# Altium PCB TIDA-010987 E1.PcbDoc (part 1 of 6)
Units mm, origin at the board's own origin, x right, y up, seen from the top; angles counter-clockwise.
Board outline 154.15 x 103.76 mm, 4 copper layers (5V, GND, MidSupply, -5V), stack 1.787 mm thick; 92 components, 52 nets, 1640 pads, 56 vias.
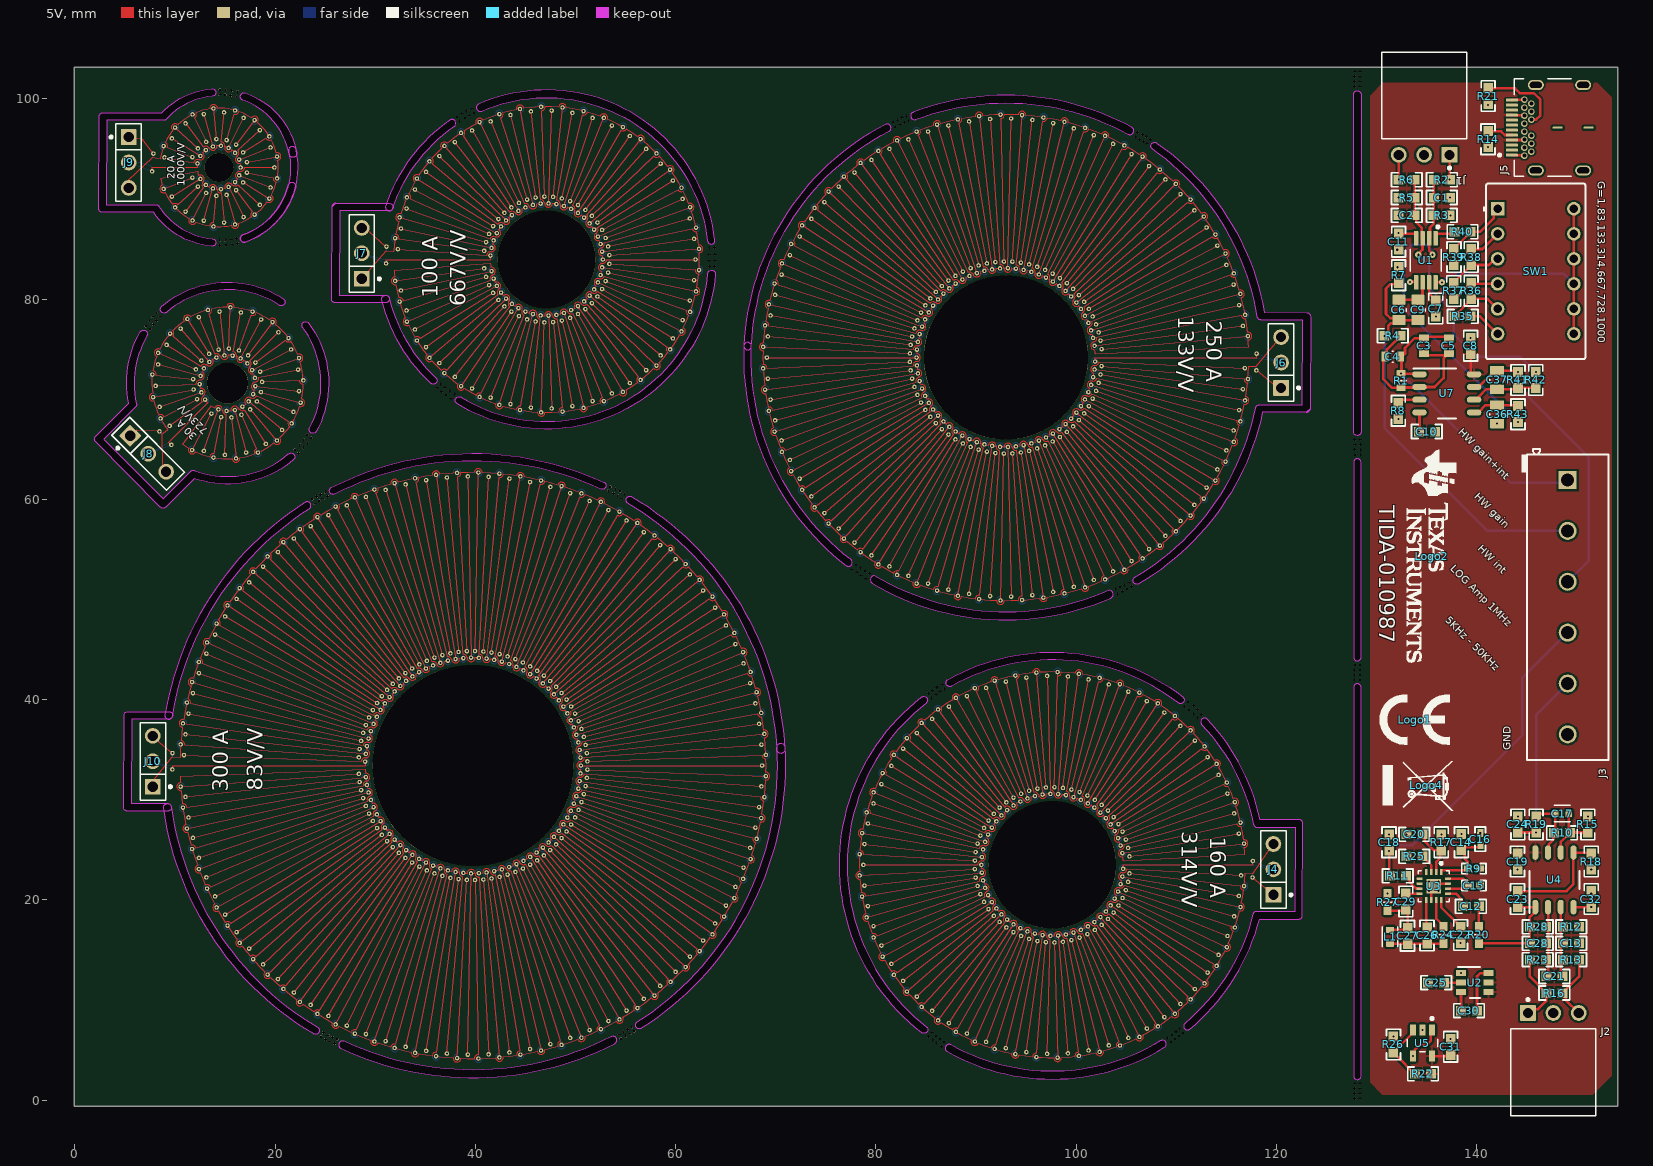
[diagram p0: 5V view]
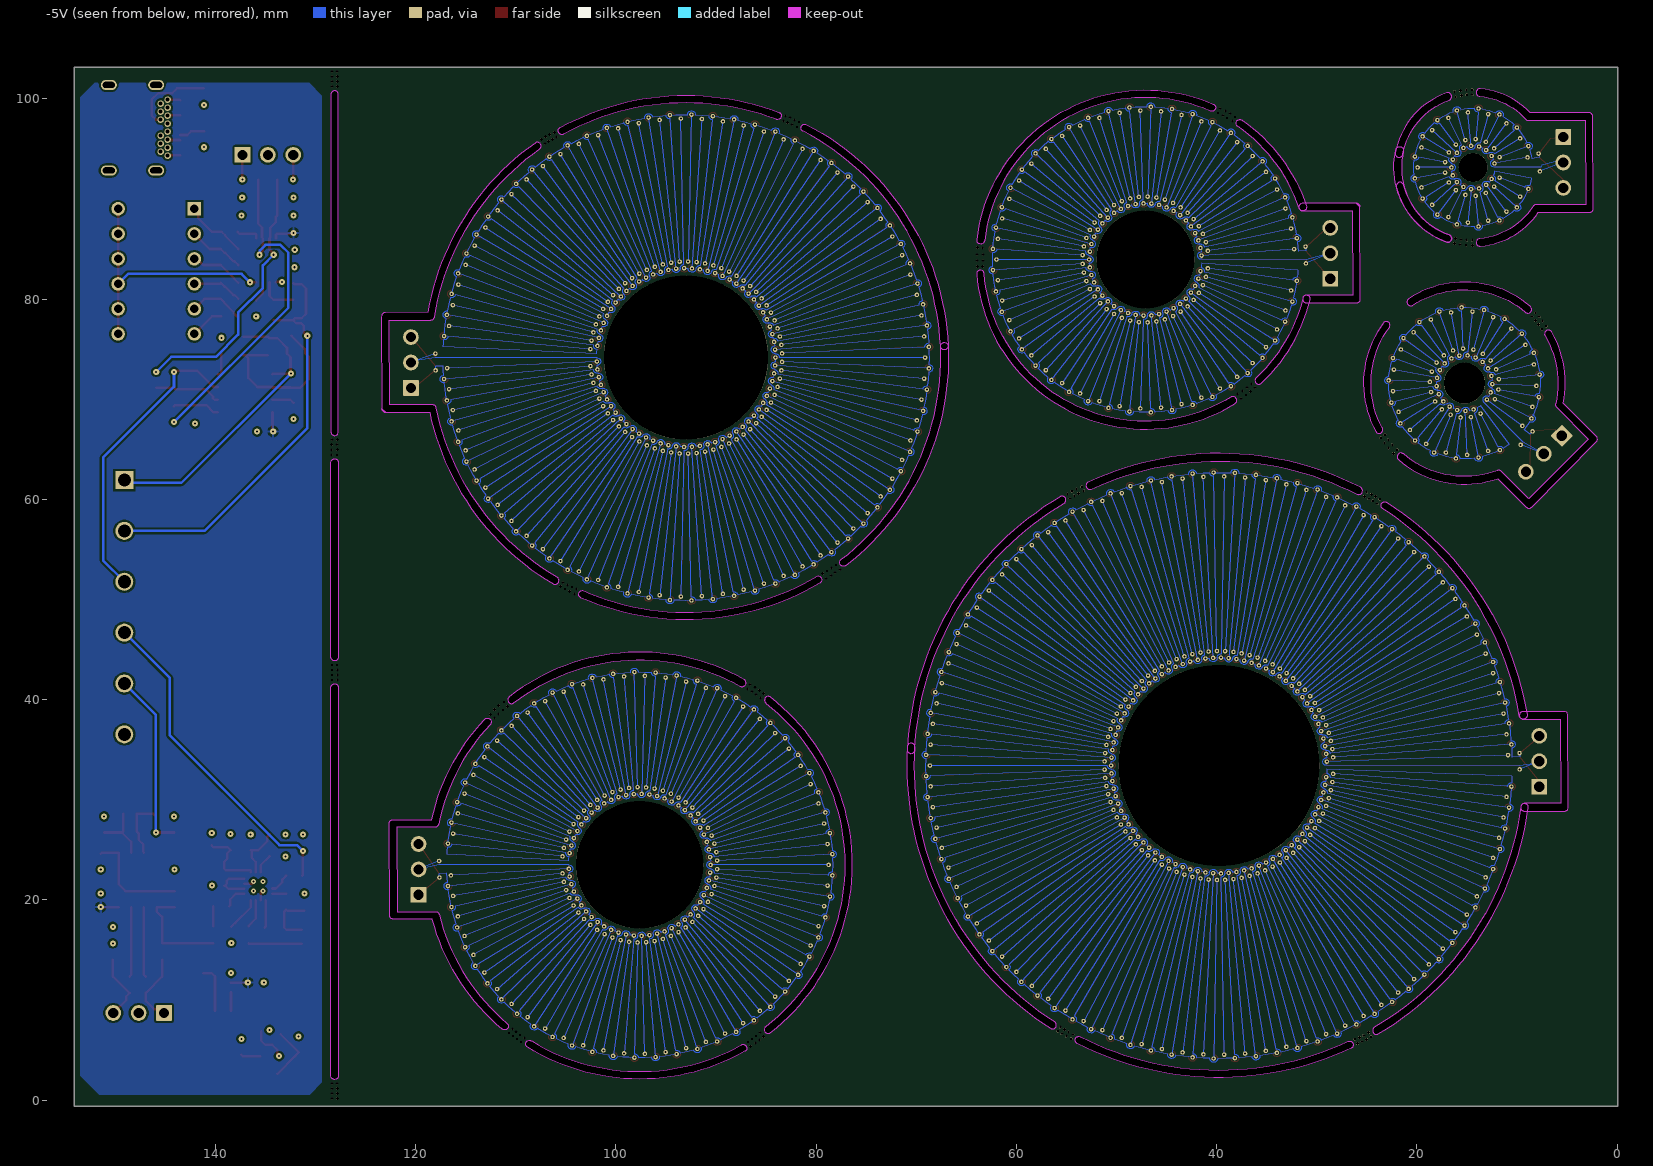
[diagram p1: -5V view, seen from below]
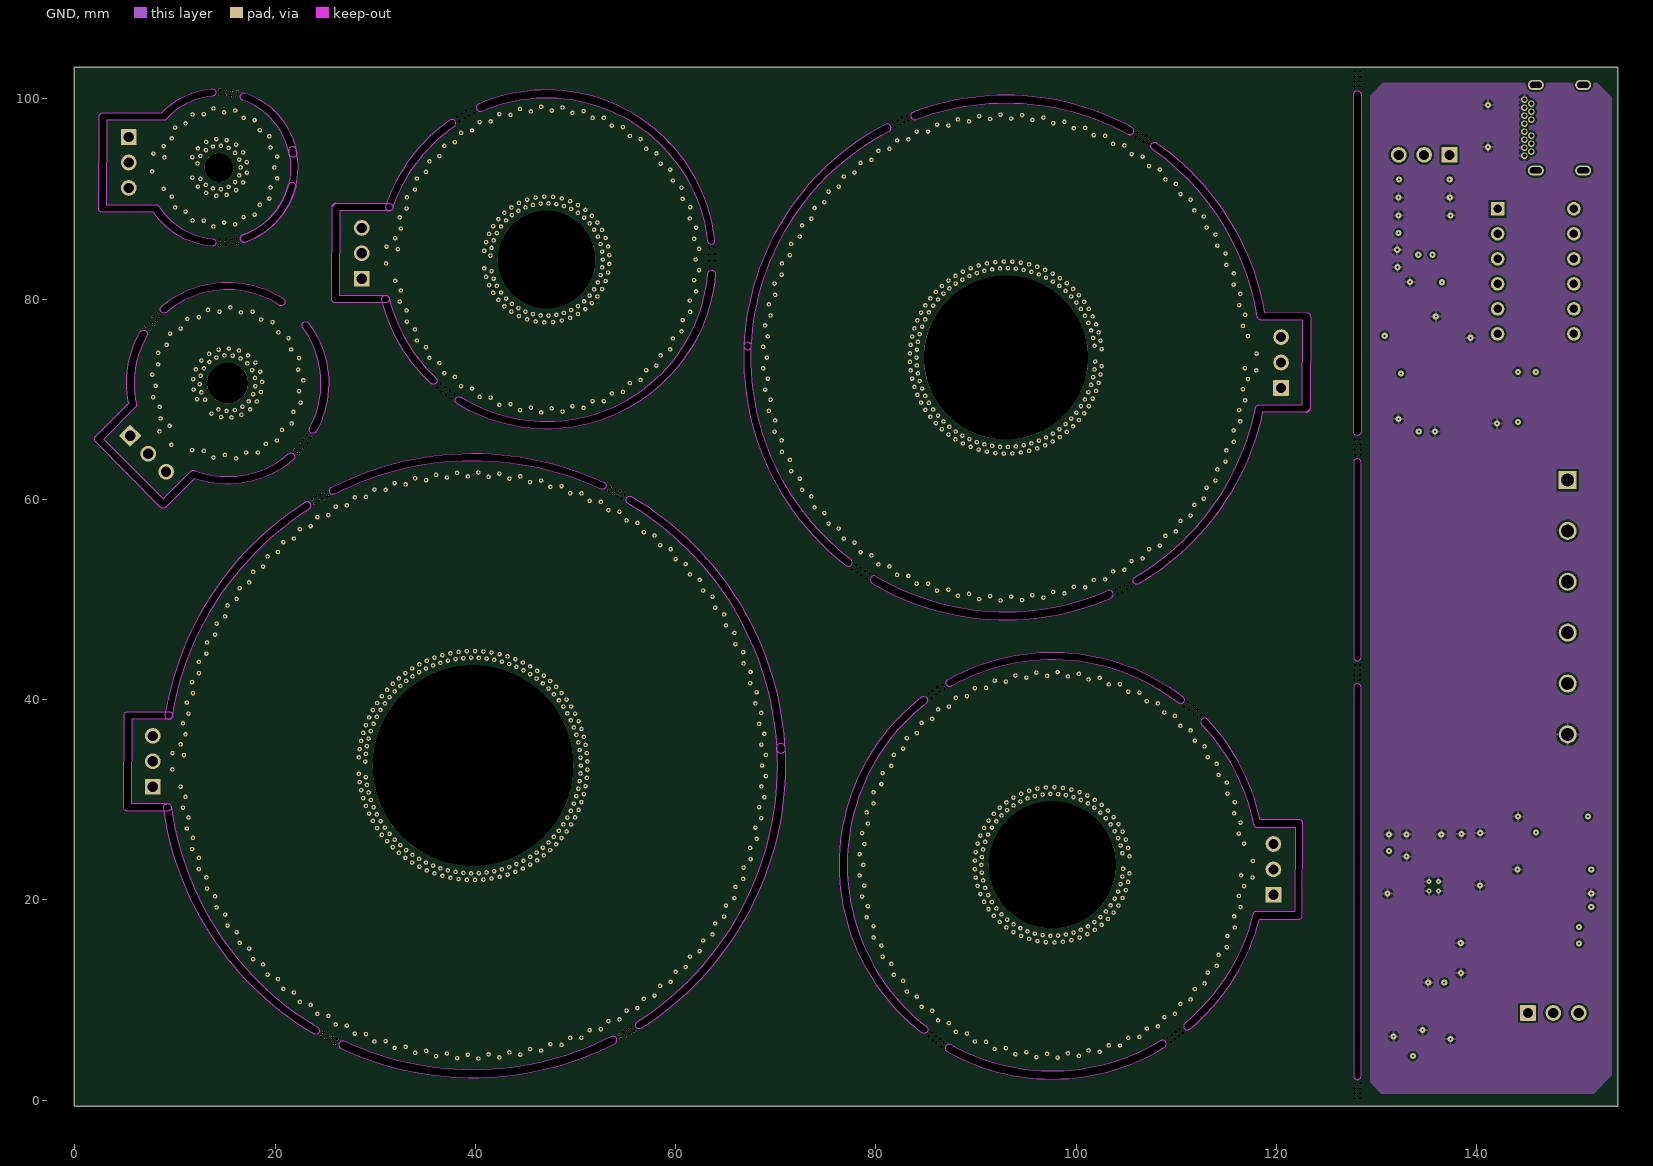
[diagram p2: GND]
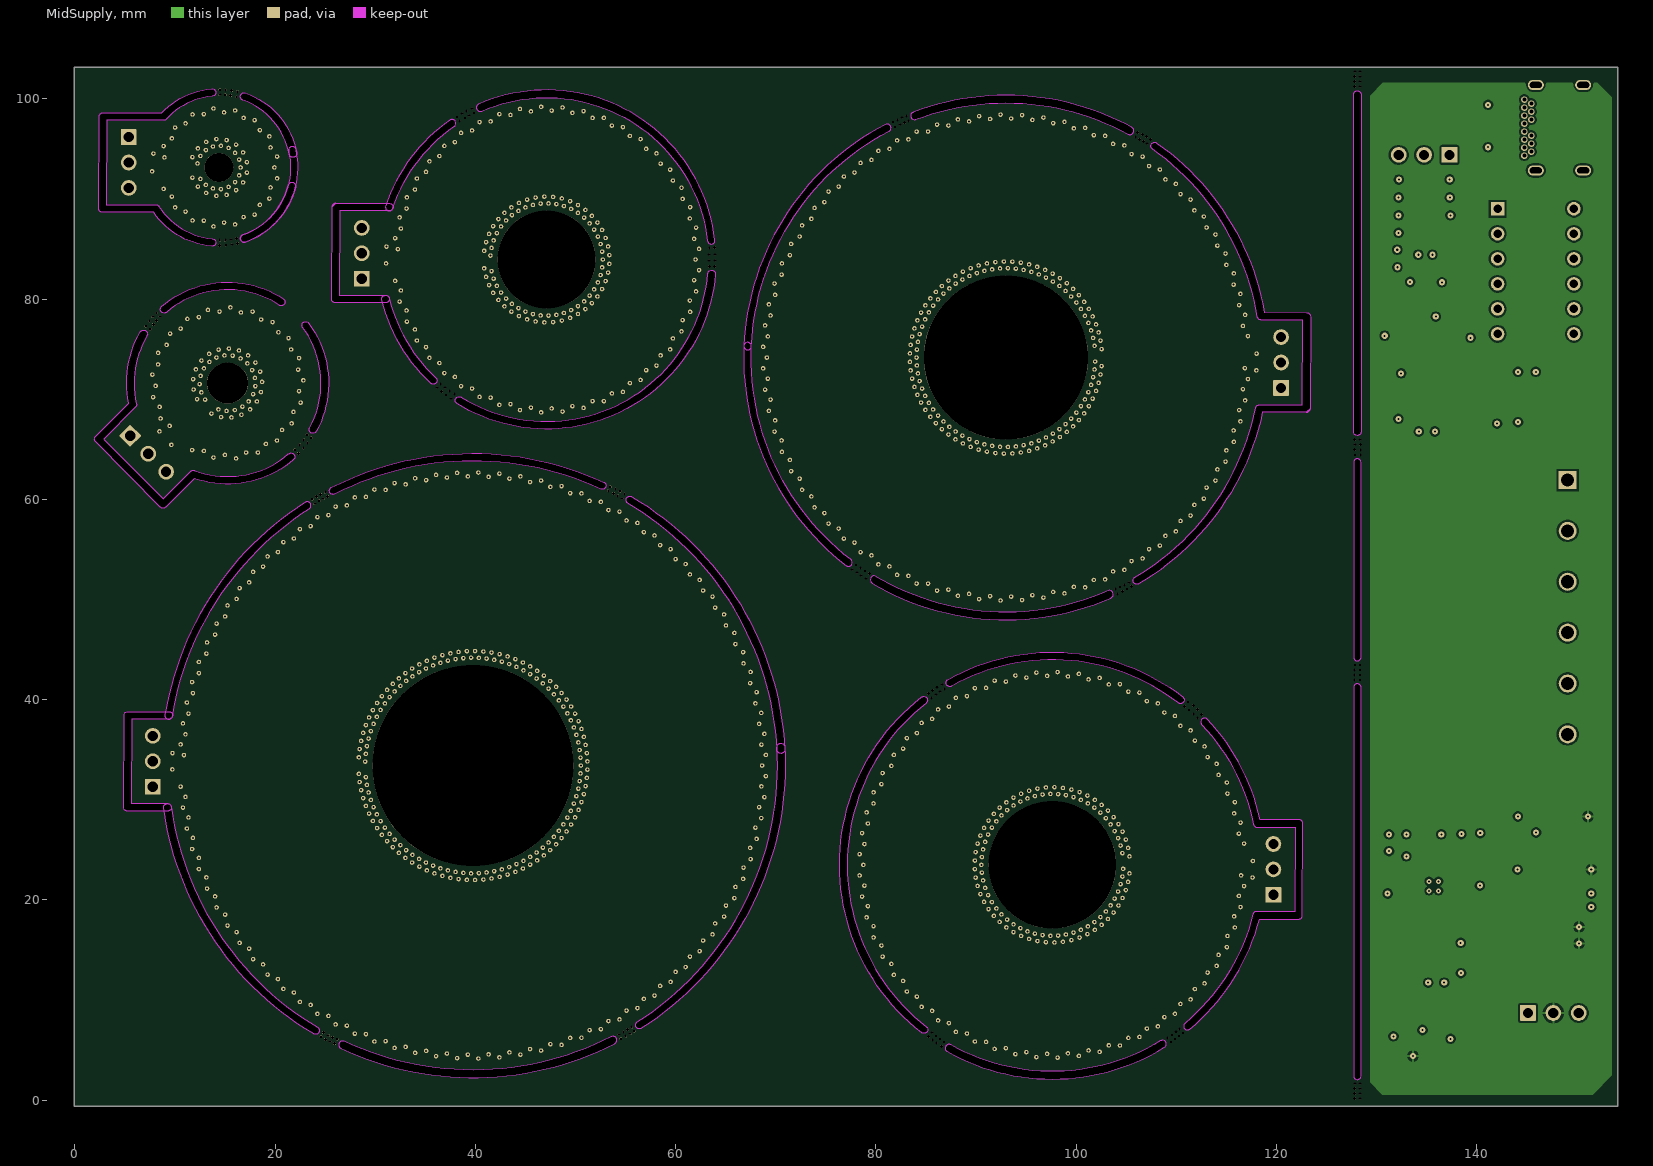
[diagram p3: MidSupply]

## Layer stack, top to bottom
Top Solder: solder mask 0.0102, Solder Resist, Dk 3.5
5V: signal copper 0.0356
Dielectric 1: prepreg 0.0711, PP-006, Dk 4.1
GND: signal copper 0.035
Dielectric1: core 1.5037, FR-4 High Tg, Dk 4.8
MidSupply: signal copper 0.035
Dielectric 2: prepreg 0.0711, PP-006, Dk 4.1
-5V: signal copper 0.0356
Bottom Solder: solder mask 0.0102, Solder Resist, Dk 3.5

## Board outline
-0.051,-0.635 154.098,-0.635 154.098,103.124 -0.051,103.124
cut-out: 63.938,85.912 ccw(c47.117,83.947) 40.343,99.469 ccw(c40.496,99.119) 40.648,98.77 cw(c47.117,83.947) 63.18,85.823 ccw(c63.559,85.868)
cut-out: 25.648,80.006 25.692,89.192 cw(c26.073,89.191) 26.075,89.572 ccw(c26.073,89.191) 25.692,89.192 26.075,89.572 31.411,89.557 cw(c31.41,89.175) 31.792,89.175 cw(c31.41,89.175) 31.409,88.794 26.453,88.808 26.413,80.385 31.04,80.385 cw(c31.04,80.004) 31.421,80.004 cw(c31.04,80.004) 31.04,79.622 26.029,79.622 cw(c26.029,80.004)
cut-out: 31.049,89.296 ccw(c31.41,89.175) 31.772,89.055 cw(c47.117,83.947) 37.904,97.239 ccw(c37.687,97.553) 38.069,97.553 ccw(c37.687,97.553) 37.47,97.866 ccw(c47.117,83.947)
cut-out: 35.537,71.589 cw(c47.117,83.947) 30.669,79.913 cw(c31.04,80.004) 31.41,80.094 ccw(c47.117,83.947) 36.059,72.146 cw(c35.798,71.867) 36.18,71.867 cw(c35.798,71.867)
cut-out: 4.88,29.242 4.924,38.427 cw(c5.305,38.426) 5.306,38.808 9.388,38.8 cw(c9.388,38.419) 9.769,38.419 cw(c9.388,38.419) 9.387,38.037 5.685,38.044 5.645,29.621 9.264,29.621 cw(c9.264,29.239) 9.646,29.239 cw(c9.264,29.239) 9.264,28.858 5.261,28.858 cw(c5.261,29.239)
cut-out: 9.011,38.481 ccw(c9.388,38.419) 9.764,38.357 cw(c39.771,33.412) 23.418,59.053 ccw(c23.213,59.374) 23.594,59.374 ccw(c23.213,59.374) 23.008,59.696 ccw(c39.771,33.412)
cut-out: 25.99,60.522 cw(c25.813,60.86) 25.636,61.198 cw(c39.771,33.412) 52.838,61.715 cw(c52.678,61.369) 53.059,61.369 cw(c52.678,61.369) 52.518,61.023 ccw(c39.771,33.412)
cut-out: 26.578,5.17 ccw(c39.771,33.412) 53.936,5.645 ccw(c53.762,5.984) 54.144,5.984 ccw(c53.762,5.984) 53.589,6.324 cw(c39.771,33.412) 26.901,5.861 ccw(c26.74,5.515)
cut-out: 23.861,6.606 cw(c39.771,33.412) 8.886,29.188 cw(c9.264,29.239) 9.642,29.291 ccw(c39.771,33.412) 24.25,7.262 cw(c24.055,6.934) 24.437,6.934 cw(c24.055,6.934)
cut-out: 84.572,6.732 cw(c97.628,23.493) 84.55,40.236 cw(c84.785,39.935) 85.166,39.935 cw(c84.785,39.935) 85.02,39.634 ccw(c97.628,23.493) 85.041,7.334 cw(c84.807,7.033) 85.188,7.033 cw(c84.807,7.033)
cut-out: 87.121,4.855 ccw(c97.628,23.493) 108.831,5.264 ccw(c108.632,5.589) 109.013,5.589 ccw(c108.631,5.589) 108.432,5.914 cw(c97.628,23.493) 87.502,5.515 ccw(c87.312,5.185)
cut-out: 87.196,42 cw(c97.628,23.493) 110.649,40.28 cw(c110.415,39.979) 110.797,39.979 cw(c110.415,39.979) 110.182,39.677 ccw(c97.628,23.493) 87.578,41.34 cw(c87.387,41.67)
cut-out: 66.823,75.311 ccw(c67.204,75.294) 67.585,75.278 cw(c92.996,74.152) 81.313,96.747 ccw(c81.138,97.085) 81.519,97.085 ccw(c81.138,97.085) 80.963,97.424 ccw(c92.996,74.152)
cut-out: 127.711,66.747 127.711,100.417 cw(c128.092,100.417) 128.474,100.417 128.474,66.747 cw(c128.092,66.747)
cut-out: 38.177,69.563 cw(c38.382,69.885) 38.588,70.206 ccw(c47.117,83.947) 58.553,72.511 ccw(c47.117,83.947) 63.226,82.519 cw(c63.607,82.492) 63.987,82.465 cw(c47.117,83.947) 59.092,71.972 cw(c47.117,83.947)
cut-out: 70.147,34.973 ccw(c39.771,33.412) 55.243,59.6 cw(c55.435,59.929) 55.627,60.259 cw(c39.771,33.412) 70.909,35.012 70.91,34.992 cw(c70.528,34.992)
cut-out: 106.252,51.554 cw(c106.066,51.888) 105.88,52.221 ccw(c92.996,74.152) 117.931,69.128 cw(c118.305,69.053) 118.305,69.434 122.611,69.447 122.651,77.875 118.479,77.902 cw(c118.481,78.284) 118.105,78.224 ccw(c92.996,74.153) 107.634,94.954 cw(c107.851,95.268) 108.068,95.582 cw(c92.996,74.153) 118.804,78.663 123.037,78.635 cw(c123.035,78.254) 123.416,78.254 123.416,78.251 123.372,69.065 cw(c122.99,69.066) 122.991,68.685 ccw(c122.99,69.066) 123.372,69.065 122.991,68.685 118.616,68.673 cw(c92.996,74.152)
cut-out: 110.88,7.678 ccw(c111.123,7.384) 111.365,7.089 ccw(c97.628,23.493) 118.325,18.069 122.228,18.063 ccw(c122.228,18.444) 122.61,18.443 122.654,27.629 122.654,27.631 ccw(c122.272,27.631) 122.272,28.013 118.387,28.013 ccw(c97.628,23.493) 113.111,38.041 ccw(c112.837,37.775) 112.564,37.509 cw(c97.628,23.493) 117.703,27.557 ccw(c118.078,27.631) 118.078,27.25 121.889,27.25 121.849,18.826 118.029,18.832 ccw(c118.029,18.451) 117.658,18.542 cw(c97.628,23.493)
cut-out: 13.669,101.013 cw(c13.704,100.633) 13.739,100.254 ccw(c14.398,93.14) 9.12,97.955 cw(c8.838,98.212) 8.838,97.83 3.194,97.839 3.154,89.415 8.091,89.415 cw(c8.091,89.034) 8.41,89.242 ccw(c14.398,93.14) 13.733,86.026 cw(c13.697,85.646) 13.662,85.267 cw(c14.398,93.14) 7.887,88.652 2.77,88.652 cw(c2.77,89.034) 2.389,89.034 2.389,89.036 2.433,98.222 cw(c2.814,98.221) 2.815,98.602 8.673,98.593 cw(c14.398,93.14)
cut-out: 21.347,64.534 cw(c21.596,64.245) 21.844,63.956 cw(c15.261,71.606) 11.941,62.075 9.087,59.222 cw(c8.817,59.491) 8.546,59.223 2.081,65.75 cw(c2.352,66.018) 1.971,66.018 cw(c2.352,66.018) 2.083,66.288 5.376,69.571 cw(c15.261,71.606) 5.169,71.606 cw(c15.261,71.606) 6.556,76.712 cw(c6.885,76.519) 7.214,76.326 ccw(c15.261,71.606) 5.932,71.606 ccw(c15.261,71.606) 6.165,69.535 cw(c5.793,69.449) 6.062,69.178 2.891,66.017 8.819,60.032 11.573,62.786 cw(c11.843,62.516) 11.978,62.873 ccw(c15.261,71.606)
cut-out: 22.1,94.929 ccw(c21.729,94.843) 21.348,94.843 21.357,94.756 cw(c14.398,93.14) 16.796,86.409 ccw(c16.924,86.05) 16.543,86.05 ccw(c16.924,86.05) 17.052,85.691 ccw(c14.398,93.14)
cut-out: 127.711,44.238 ccw(c128.092,44.238) 128.474,44.238 128.474,63.662 ccw(c128.092,63.662) 127.711,63.662
cut-out: 127.711,2.429 ccw(c128.092,2.429) 128.474,2.429 128.474,41.204 ccw(c128.092,41.204) 127.711,41.204
cut-out: 21.321,91.373 cw(c21.69,91.278) 22.06,91.184 cw(c14.398,93.14) 17.052,85.691 cw(c16.924,86.05) 16.543,86.05 cw(c16.924,86.05) 16.796,86.409 ccw(c14.398,93.14)
cut-out: 17.052,100.588 cw(c14.398,93.14) 22.171,94.593 cw(c21.796,94.522) 21.421,94.452 ccw(c14.398,93.14) 16.796,99.87 cw(c16.924,100.229) 16.543,100.229 cw(c16.924,100.229)
cut-out: 20.412,79.384 ccw(c15.261,71.606) 9.176,78.677 cw(c8.927,78.966) 8.678,79.255 cw(c15.261,71.606) 20.833,80.02 20.893,79.972 cw(c20.623,79.702)
cut-out: 24.124,66.779 cw(c23.792,66.965) 23.459,67.151 ccw(c15.261,71.606) 22.768,77.146 cw(c23.075,77.372) 23.344,77.642 23.381,77.599 cw(c15.261,71.606)
cut-out: 56.593,7.16 cw(c56.389,7.483) 56.185,7.805 ccw(c39.771,33.412) 70.187,33.412 ccw(c39.779,33.413) 70.132,35.238 cw(c70.513,35.261) 70.894,35.284 cw(c39.779,33.413) 70.95,33.412 cw(c39.771,33.412)
cut-out: 105.202,96.468 ccw(c105.388,96.802) 105.574,97.135 ccw(c92.996,74.153) 92.996,100.351 ccw(c92.996,74.154) 83.722,98.655 ccw(c83.862,98.3) 84.002,97.945 cw(c92.996,74.153) 92.996,99.589 cw(c92.996,74.152)
cut-out: 77.035,53.377 ccw(c77.263,53.683) 77.491,53.989 cw(c92.996,74.152) 67.585,75.278 ccw(c67.204,75.295) 67.204,75.676 ccw(c67.204,75.295) 66.823,75.311 ccw(c92.996,74.152)
cut-out: 103.473,50.139 ccw(c103.31,50.503) 103.31,50.901 cw(c92.996,74.151) 79.868,52.366 ccw(c79.868,51.955) 79.653,51.606 ccw(c92.996,74.152)

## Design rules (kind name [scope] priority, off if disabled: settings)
AcuteAngle [All] p1: minimum=4.50000000000000E+0001 checktracksonly=FALSE
AssemblyTestPointUsage [All] p1: valid=2
BoardOutlineClearance BoardOutlineClearance_MountingHoles [OnCopper and InComponentClass('Mounting Holes')] p1: gap=0.254 ignorepadtopadclearanceinfootprint=FALSE
BoardOutlineClearance BoardOutlineClearance_Poly [OnCopper and IsPoly] p2: gap=0.254 ignorepadtopadclearanceinfootprint=FALSE
BoardOutlineClearance [OnCopper and Not InComponentClass('Logo') and not InComponentClass('FiducialMark') and not InRegion(1000,500,4000,800) and not InPoly] p3: gap=0.254 ignorepadtopadclearanceinfootprint=FALSE
Clearance Clearance_Keepouts [((IsTrack Or IsArc) And Not InPoly) And IsFree and IsKeepOut vs ((IsTrack Or IsArc) And Not InPoly) And IsFree and IsKeepOut] p1: gap=0 ignorepadtopadclearanceinfootprint=FALSE
Clearance Clearance_Poly [InPolygon] p2: gap=0.2 ignorepadtopadclearanceinfootprint=TRUE
Clearance Clearance_FiducialMark [IsKeepOut and InComponentClass('FiducialMark') vs IsPad and InComponentClass('FiducialMark')] p3: gap=0 ignorepadtopadclearanceinfootprint=FALSE
Clearance [All] p4: gap=0.2 ignorepadtopadclearanceinfootprint=TRUE
ComponentClearance ComponentClearance_MountingHoles_FiducialMarks [InComponentClass('Mounting Holes') vs InComponentClass('FiducialMark')] p1: gap=1.27 collisioncheckmode=3 verticalgap=0.254 showdistances=FALSE
ComponentClearance ComponentClearance_Shunt [InComponentClass('Header') vs InComponentClass('Shunt')] p2: gap=0 collisioncheckmode=3 verticalgap=0 showdistances=FALSE
ComponentClearance ComponentClearance_Logo [InComponentClass('Logo')] p3: gap=0.762 collisioncheckmode=3 verticalgap=0.254 showdistances=FALSE
ComponentClearance ComponentClearance_ScrewToNut [(HasFootprint('NY PMS 440 0025 PH')) vs (HasFootprint('Keystone_1902C'))] p4: gap=0.127 collisioncheckmode=3 verticalgap=0.254 showdistances=FALSE
ComponentClearance ComponentClearance_MountingHoles [InComponentClass('Mounting Holes')] p5: gap=2.54 collisioncheckmode=3 verticalgap=2540 showdistances=FALSE
ComponentClearance ComponentClearance_SmallPassives [HasFootprint('0201*') or HasFootprint('0402*') or HasFootprint('0508') or HasFootprint('0603*') or HasFootprint('0612') or HasFootprint('0805*') or HasFootprint('0815*') or HasFootprint('0830*') or HasFootprint('1206*') or HasFootprint('1210*') or HasFootprint('1808*') or HasFootprint('1812*') or HasFootprint('1825*') or HasFootprint('2010*') or HasFootprint('2220*') or HasFootprint('2225*') or HasFootprint('2512*') or HasFootprint('2728*') or HasFootprint('3518*') vs HasFootprint('0201*') or HasFootprint('0402*') or HasFootprint('0508') or HasFootprint('0603*') or HasFootprint('0612') or HasFootprint('0805*') or HasFootprint('0815*') or HasFootprint('0830*') or HasFootprint('1206*') or HasFootprint('1210*') or HasFootprint('1808*') or HasFootprint('1812*') or HasFootprint('1825*') or HasFootprint('2010*') or HasFootprint('2220*') or HasFootprint('2225*') or HasFootprint('2512*') or HasFootprint('2728*') or HasFootprint('3518*')] p6: gap=0.38 collisioncheckmode=3 verticalgap=0.254 showdistances=FALSE
ComponentClearance ComponentClearance_THtoSMT [IsThruComponent vs IsSMTComponent] p7: gap=0.762 collisioncheckmode=3 verticalgap=0.762 showdistances=FALSE
ComponentClearance ComponentClearance_THtoTH [IsThruComponent vs IsThruComponent] p8: gap=0.508 collisioncheckmode=3 verticalgap=0.762 showdistances=FALSE
ComponentClearance [All] p9: gap=0.508 collisioncheckmode=3 verticalgap=0.254 showdistances=FALSE
DiffPairsRouting [All] p1: maxlimit=2.54 minlimit=0.254 mostfreqgap=0.254 toplayer_minwidth=0.381 toplayer_maxwidth=0.381 toplayer_prefwidth=0.381 midlayer1_minwidth=0.381 midlayer1_maxwidth=0.381 midlayer1_prefwidth=0.381 midlayer2_minwidth=0.381 midlayer2_maxwidth=0.381 midlayer2_prefwidth=0.381 bottomlayer_minwidth=0.381 bottomlayer_maxwidth=0.381 bottomlayer_prefwidth=0.381 maxuncoupledlength=25.4
FabricationTestPointUsage TestPointUsage [All] p1: valid=2 allowmultiple=FALSE
FabricationTestpoint Testpoint [All] p1: side=3 testpointundercomponent=TRUE minsize=1.016 maxsize=2.54 preferedsize=1.524 minholesize=0 maxholesize=1.016 preferedholesize=0.813 testpointgrid=0.025 allowsidetop=TRUE allowsidebottom=TRUE usegrid=TRUE gridtolerance=0
FanoutControl Fanout_LCC [IsLCC] p1: bgadir=Out bgaviamode=Centered fanoutstyle=Auto fanoutdirection=Alternating viagrid=0.025 // Fanout_LCC (Default Rule)
FanoutControl Fanout_BGA [IsBGA] p2: bgadir=Out bgaviamode=Centered fanoutstyle=Auto fanoutdirection=Alternating viagrid=0.025 // Fanout_BGA (Default Rule)
FanoutControl Fanout_Default [All] p4: bgadir=Out bgaviamode=Centered fanoutstyle=Auto fanoutdirection=Alternating viagrid=0.025 // Fanout_Default (Default Rule)
FanoutControl Fanout_Small [(CompPinCount < 5)] p5: bgadir=Out bgaviamode=Centered fanoutstyle=Auto fanoutdirection=OutThenIn viagrid=0.025 // Fanout_Small (Default Rule)
HoleSize [All] p1: absolutevalues=TRUE maxlimit=6.375 minlimit=0.2 maxpercent=80.000 minpercent=20.000
MinimumAnnularRing MinimumAnnularRing_ThermalPadVias [IsVia and InAnyComponent] p1: minimumring=0.15
MinimumAnnularRing [All] p2: minimumring=0.2
MinimumSolderMaskSliver MinimumSolderMaskSliver_Logo [InComponentClass('Logo') vs InComponentClass('Logo')] p1: minsoldermaskwidth=0.018
MinimumSolderMaskSliver [All] p2: minsoldermaskwidth=0.1
PlaneConnect [All] p1: planeconnectstyle=Relief reliefexpansion=0.254 reliefentries=4 reliefconductorwidth=0.254 reliefairgap=0.254
PolygonConnect [All] p1: connectstyle=Relief reliefconductorwidth=0.254 reliefentries=4 polygonreliefangle="90 Angle" airgapwidth=0.254
RoutingLayers [All] p1: top layer_v5=TRUE mid layer 1_v5=FALSE mid layer 2_v5=FALSE bottom layer_v5=TRUE
RoutingVias ThermalPadVias [IsVia and InAnyComponent] p1: holewidth=0.2 width=0.5 viastyle="Through Hole" minholewidth=0.2 minwidth=0.5 maxholewidth=0.33 maxwidth=0.6
RoutingVias [All] p2: holewidth=0.406 width=0.864 viastyle="Through Hole" minholewidth=0.2 minwidth=0.61 maxholewidth=1.016 maxwidth=1.651
SilkToBoardRegionClearance [Not ((IsComment or IsDesignator) And (Hide <> 'False')) and not InRegion(1000,500,4000,800)] p1:
SilkToSilkClearance SilkToSilkClearance_Pb-FreeLogo [(HasFootprint('Pb-Free_Overlay_Medium') OR HasFootprint('Pb-Free_Overlay_Small')) vs (HasFootprint('Pb-Free_Overlay_Medium') OR HasFootprint('Pb-Free_Overlay_Small'))] p1: silktosilkclearance=0
SilkToSilkClearance [All] p2: silktosilkclearance=0.1
SilkToSolderMaskClearance SilkToComponentPadClearance [(IsPad or IsFill or IsRegion) and InAnycomponent] p1: minsilkscreentomaskgap=0.127 clearancetoexposedcopper=TRUE
SilkToSolderMaskClearance "Silk to Solder Mask Opening" [All] p2: minsilkscreentomaskgap=0.1 clearancetoexposedcopper=FALSE
SolderMaskExpansion [All] p1: expansion=0.05 istentingtop=FALSE
SupplyNets "Schematic Supply Nets_8" [InNet('INT-input-P')] p1: voltage=0.000
SupplyNets "Schematic Supply Nets_5" [InNet('INT-input-N')] p2: voltage=0.000
SupplyNets "Schematic Supply Nets_20" [InNet('int_amp_out')] p3: voltage=0.000
SupplyNets "Schematic Supply Nets_19" [InNet('amp_out')] p4: voltage=0.000
SupplyNets "Schematic Supply Nets_18" [InNet('int_out')] p5: voltage=0.000
SupplyNets "Schematic Supply Nets_17" [InNet('Main_out')] p6: voltage=0.000
SupplyNets "Schematic Supply Nets_16" [InNet('Log_out')] p7: voltage=0.000
SupplyNets "Schematic Supply Nets_15" [InNet('LNA_O')] p8: voltage=0.000
SupplyNets "Schematic Supply Nets_13" [InNet('1_RG_P1')] p9: voltage=0.000
SupplyNets "Schematic Supply Nets_11" [InNet('intOut')] p10: voltage=0.000
SupplyNets "Schematic Supply Nets_10" [InNet('INPUT_2_P')] p11: voltage=0.000
SupplyNets "Schematic Supply Nets_9" [InNet('INPUT_2_N')] p12: voltage=0.000
SupplyNets "Schematic Supply Nets_7" [InNet('MidSupply')] p13: voltage=0.000
SupplyNets "Schematic Supply Nets_6" [InNet('2_RG_P1')] p14: voltage=0.000
SupplyNets "Schematic Supply Nets_4" [InNet('5V')] p15: voltage=0.000
SupplyNets "Schematic Supply Nets_3" [InNet('INPUT_1_N')] p16: voltage=0.000
SupplyNets "Schematic Supply Nets_2" [InNet('INPUT_1_P')] p17: voltage=0.000
SupplyNets "Schematic Supply Nets_1" [InNet('GND')] p18: voltage=0.000
SupplyNets "Schematic Supply Nets" [InNet('-5V')] p19: voltage=0.000
UnRoutedNet [All] p1: checkbadconnections=TRUE
Width [All] p1: maxlimit=2.54 minlimit=0.152 preferedwidth=0.254 checkconnectedcopper=TRUE
13 further rules are at their usual default settings.

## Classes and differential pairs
component class "TIDA-010987_Power E1": C25 C30 C31 J5 R14 R21 R22 R26 U2 U5
component class "TIDA-010987_AFE E1": C1 C2 C3 C4 C5 C6 C7 C8 C9 C10 C11 C12 C13 C14 C15 C16 C17 C18 C19 C20 C21 C22 C23 C24 C26 C27 C28 C29 C32 C36 C37 J1 J2 J3 J4 J6 J7 J8 J9 J10 L1 R1 R2 R3 R4 R5 R6 R7 R8 R9 R10 R11 R12 R13 R15 R16 R17 R18 R19 R20 R23 R24 R25 R27 R28 R35 R36 R37 R38 R39 R40 R41 R42 R43 SW1 U1 U3 U4 U7
component class Logo: Logo2
component class "TIDA-010987_Hardware E1": Logo1 Logo2 Logo4

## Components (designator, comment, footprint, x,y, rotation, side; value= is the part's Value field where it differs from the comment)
C1 "C0603H103J3GACTU" 0603 136.523,90.137 r0 top value=0.01uF
C2 "C0603H103J3GACTU" 0603 133.02,88.359 r0 top value=0.01uF
C3 "GRMJN65C1H104GE01J" FP-GRMJN65C1H104GE01J_0704-MFG 134.758,75.33 r90 top value=100nF
C4 "GRMJN65C1H104GE01J" FP-GRMJN65C1H104GE01J_0704-MFG 131.623,74.247 r0 top value=100nF
C5 "GRMJN65C1H104GE01J" FP-GRMJN65C1H104GE01J_0704-MFG 137.221,75.33 r90 top value=100nF
C6 "GMC21X5R226M35NT" FP-GMC21X5R226M35NT_0805-MFG 132.246,78.913 r90 top value=22µF
C7 "06035C104JAT2A" 0603 135.924,79.046 r90 top value=0.1uF
C8 "06035C104JAT2A" 0603 139.405,75.33 r270 top value=0.1uF
C9 "GMC21X5R226M35NT" FP-GMC21X5R226M35NT_0805-MFG 134.152,78.913 r270 top value=22µF
C10 "06035C104JAT2A" 0603 135.027,66.769 r180 top value=0.1uF
C11 "06035C104JAT2A" 0603 132.211,85.727 r270 top value=0.1uF
C12 "GRM1885C1E102JA01D" 0603 139.431,19.348 r0 top value=1000pF
C13 "C0603C271J5GACTU" 0603 149.444,15.646 r180 top value=270pF
C14 "GRM188Z71A106MA73D" 0603 138.481,25.762 r270 top value=10uF
C15 "0402B103K6R3CT" 0402 139.731,21.423 r0 top value=0.01uF
C16 "GRM155R70J103KA01D" 0402 140.366,26.062 r270 top value=0.01uF
C17 "GCM1885C2A471JA16D" FP-GCM1885C2A471JA16D_0603-MFG 148.531,28.6 r180 top value=470pF
C18 "GRM1885C1H470JA01D" 0603 131.255,25.737 r90 top value=47pF
C19 "06035C104JAT2A" 0603 144.086,23.818 r90 top value=0.1uF
C20 "GRM1885C1E102JA01D" 0603 133.781,26.537 r0 top value=1000pF
C21 "GRM1885C1H151JA01D" 0603 147.769,12.344 r180 top value=150pF
C22 "06035C104JAT2A" 0603 138.415,16.496 r90 top value=0.1uF
C23 "06035A101JAT2A" 0603 144.086,20.079 r270 top value=100pF
C24 "06035A101JAT2A" 0603 144.123,27.524 r90 top value=100pF
C25 "C1608X7S1A335K080AC" 0603 135.967,11.731 r0 top value=3.3uF
C26 "06035A101JAT2A" 0603 135.052,16.438 r90 top value=100pF
C27 "GRM1885C1H331JA01D" 0603 133.105,16.409 r90 top value=330pF
C28 "C0603C271J5GACTU" 0603 146.116,15.646 r0 top value=270pF
C29 "06035A101JAT2A" 0603 132.93,19.823 r90 top value=100pF
C30 "C1608X7S1A335K080AC" 0603 139.239,8.937 r0 top value=3.3uF
C31 "06035C104JAT2A" 0603 137.402,5.32 r90 top value=0.1uF
C32 "06035C104JAT2A" 0603 151.452,20.079 r270 top value=0.1uF
C36 "AC0805KRX7R8BB104" FP-AC0805KRX7R8BB104_0805-MFG 142.047,68.484 r90 top value=100nF
C37 "AC0805KRX7R8BB104" FP-AC0805KRX7R8BB104_0805-MFG 142.047,71.92 r90 top value=100nF
J1 "PPTC031LGBN-RC" FP-PPTC031LGBN-RC_HDR3-MFG 134.758,100.247 r180 top
J2 "PPTC031LGBN-RC" FP-PPTC031LGBN-RC_HDR3-MFG 147.666,2.851 r0 top
J3 "1729160" Phoenix_1729160 149.098,49.225 r270 top
J4 "HTSW-103-07-F-S" FP-HTSW-103-07-F-S_HDR3-MFG 119.71,23.038 r90 top
J5 "632723300011" FP-632723300011_CONN_USB_8MM74_11MM20-MFG 149.448,97.11 r90 top
J6 "HTSW-103-07-F-S" FP-HTSW-103-07-F-S_HDR3-MFG 120.472,73.66 r90 top
J7 "HTSW-103-07-F-S" FP-HTSW-103-07-F-S_HDR3-MFG 28.661,84.562 r90 top
J8 "HTSW-103-07-F-S" FP-HTSW-103-07-F-S_HDR3-MFG 7.331,64.551 r315 top
J9 "HTSW-103-07-F-S" FP-HTSW-103-07-F-S_HDR3-MFG 5.383,93.636 r270 top
J10 "HTSW-103-07-F-S" FP-HTSW-103-07-F-S_HDR3-MFG 7.798,33.833 r90 top
L1 "MLF1608DR68MTA00" FP-MLF1608DR68MTA00_0603-MFG 131.355,16.311 r270 top value=680nH
Logo1 "CE Mark" CE_Mark_5mm 133.816,37.996 r0 top
Logo2 "Texas Instruments" TI_Stacked_Overlay_Small 135.496,54.311 r270 top
Logo4 "WEEE logo" WEEE_Minimum 134.993,31.439 r270 top
R1 "ERA-3AEB104V" FP-ERA-3AEB104V_0603-MFG 132.47,71.845 r270 top value=100k
R2 "RT0603BRD0716KL" 0603 136.534,91.915 r0 top value=16.0k
R3 "RT0603BRD0747K5L" 0603 136.515,88.359 r180 top value=47.5k
R4 "RT0603BRD078K87L" 0603 131.623,76.33 r0 top value=8.87k
R5 "RT0603BRD0747K5L" 0603 133.02,90.137 r180 top value=47.5k
R6 "RT0603BRD0716KL" 0603 133.02,91.915 r180 top value=16.0k
R7 "RT0603BRD0750K5L" 0603 132.22,82.384 r90 top value=50.5k
R8 "RT0603BRD079K88L" 0603 132.191,68.831 r90 top value=9.88k
R9 "MCR01MZPF10R0" 0402 139.731,23.114 r0 top value=10.0
R10 "RT0603BRD076K49L" 0603 148.531,26.695 r180 top value=6.49k
R11 "RG1608P-511-B-T5" 0603 132.13,22.389 r180 top value=510
R12 "RT0603BRD07562KL" 0603 149.444,17.297 r0 top value=562k
R13 "RG1608P-2210-B-T5" 0603 149.444,14.028 r180 top value=221
R14 "RG1608P-512-B-T5" 0603 141.141,95.961 r270 top value=5.10k
R15 "RC0603FR-07402RL" 0603 151.109,27.524 r270 top value=402
R16 "RG1608P-2210-B-T5" 0603 147.769,10.693 r0 top value=221
R17 "RC0603FR-0730KL" 0603 136.472,25.737 r270 top value=30.0k
R18 "RG1608P-274-B-T5" 0603 151.452,23.817 r270 top value=270k
R19 "RC0603FR-0731K6L" 0603 145.941,27.524 r270 top value=31.6k
R20 "RC0603FR-100RL" FP-RC0603FR-100RL_0603-MFG 140.231,16.496 r90 top value=0
R21 "RG1608P-512-B-T5" 0603 141.152,100.27 r270 top value=5.10k
R22 "M55342K12B10E0T" 0603 134.646,2.613 r0 top value=10.0k
R23 "RG1608P-2210-B-T5" 0603 146.116,14.028 r0 top value=221
R24 "RC0603FR-100RL" FP-RC0603FR-100RL_0603-MFG 136.691,16.496 r270 top value=0
R25 "RG1608P-563-B-T5" 0603 133.781,24.34 r180 top value=56.0k
R26 "M55342K12B10E0T" 0603 131.699,5.561 r270 top value=10.0k
R27 "RC0603FR-100RL" FP-RC0603FR-100RL_0603-MFG 131.116,19.778 r270 top value=0
R28 "RT0603BRD07562KL" 0603 146.116,17.297 r180 top value=562k
R35 "RT0603BRD07294RL" 0603 138.605,78.271 r0 top value=294
R36 "RT0603BRD0735R2L" 0603 139.459,80.815 r270 top value=35.2
R37 "RT0603BRD0735R2L" 0603 137.718,80.808 r270 top value=35.2
R38 "RT0603BRD0730R5L" 0603 139.456,84.197 r270 top value=30.5
R39 "RT0603BRD0710RL" 0603 137.741,84.197 r270 top value=10.0
R40 "ERA-3AEB101V" 0603 138.59,86.716 r0 top value=100
R41 "RT0603BRD07470KL" 0603 144.135,71.92 r90 top value=470k
R42 "RG1608P-4752-B-T5" 0603 145.91,71.92 r270 top value=47.5k
R43 "RG1608P-4752-B-T5" 0603 144.135,68.506 r90 top value=47.5k
SW1 "76SB06ST" SW_76SB06 145.91,82.764 r0 top
U1 "INA333AIDGKT" DGK0008A-MFG 134.924,83.864 r270 top
U2 "LM2664M6/NOPB" DBV0006A_N 139.815,11.731 r0 top
U3 "LOG300RGT" RGT0016A-MFG 135.722,21.373 r270 top
U4 "TLV9002IDR" D0008A_N 147.769,21.996 r90 top
U5 "TL081HIDBVR" DBV0005A-MFG 134.596,5.695 r270 top
U7 "TLV9002IDR" D0008A_N 137.023,70.579 r0 top

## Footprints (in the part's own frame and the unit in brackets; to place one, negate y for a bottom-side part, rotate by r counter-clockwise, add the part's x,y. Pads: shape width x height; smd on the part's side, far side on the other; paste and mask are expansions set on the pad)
0402 [mm] "0402 from SM-752 data"
  rect 0.8x0.6 smd: 1(-0.6,0) 2(0.6,0)
  silkscreen extent -1.22,-0.52 1.22,0.52, body extent -0.55,-0.3 0.55,0.3, height 0.6
0603 [mm] "0603 from SM-752 data"
  rect 1x0.95 smd: 1(-0.8,0) 2(0.8,0)
  silkscreen extent -1.52,-0.69 1.52,0.69, body extent -0.87,-0.47 0.87,0.47, height 1
CE_Mark_5mm [mm] "Minimum text height for CE Mark"
  silkscreen extent -3.5,-2.5 3.5,2.5
D0008A_N [mm] "SOIC, 8-Leads, Body 4.9x3.9mm, Pitch 1.27mm, IPC Medium Density"
  oval 1.45x0.6 smd: 1(-2.725,1.905) 2(-2.725,0.635) 3(-2.725,-0.635) 4(-2.725,-1.905) 5(2.725,-1.905) 6(2.725,-0.635) 7(2.725,0.635) 8(2.725,1.905)
  silkscreen extent -3.3,-2.5 0.9,2.5, body extent -3,-2.45 3,2.45, height 1.63
DBV0005A-MFG [mm]
  rrect17% 1.1x0.6 smd paste+0 mask+0: 1(-1.3,0.95) 2(-1.3,0) 3(-1.3,-0.95) 4(1.3,-0.95) 5(1.3,0.95)
  silkscreen extent -2.57,-1.52 0.88,1.53, body extent -1.95,-1.78 1.95,1.78, height 0.25
DBV0006A_N [mm] "SOT23, 6-Leads, Body 2.9x1.6mm, Pitch 0.95mm, Lead Span 2.8mm, IPC Medium Density"
  rrect17% 1x0.6 smd: 1(-1.375,0.95) 2(-1.375,0) 3(-1.375,-0.95) 4(1.375,-0.95) 5(1.375,0) 6(1.375,0.95)
  silkscreen extent -1.67,-1.55 0.5,1.55, body extent -1.42,-1.46 1.42,1.46, height 1.12
DGK0008A-MFG [mm]
  rrect22% 1.45x0.45 smd paste+0 mask+0: 1(-2.2,0.975) 2(-2.2,0.325) 3(-2.2,-0.325) 4(-2.2,-0.975) 5(2.2,-0.975) 6(2.2,-0.325) 7(2.2,0.325) 8(2.2,0.975)
  silkscreen extent -3.47,-1.55 1.1,1.55, body extent -3.03,-1.8 3.03,1.8, height 0.25
FP-632723300011_CONN_USB_8MM74_11MM20-MFG [mm]
  round 0.65 hole 0.4 paste-2539.97 mask+0: 1(-2,4.68) 2(2,4.68) B1(2.8,4.68) B2(2.4,3.98) B3(1.6,3.98) B4(1.2,4.68) B5(0.8,3.98) B6(0.4,4.68) B7(-0.4,4.68) B8(-0.8,3.98) B9(-1.2,4.68) B10(-1.6,3.98) B11(-2.4,3.98) B12(-2.8,4.68)
  rrect100% 1x1.6 hole 1.2 slot 0.6 at 0 deg paste-2539.97 mask+0: 3(-4.27,3.53) 4(4.27,3.53) 6(-4.27,-1.2) 7(4.27,-1.2)
  rrect50% 0.2x1 smd paste+0 mask+0: 5(0,1.35) 8(0,-1.75)
  rrect33% 0.3x1.2 smd paste+0 mask+0: A1(-2.75,5.93) A2(-2.25,5.93) A3(-1.75,5.93) A4(-1.25,5.93) A5(-0.75,5.93) A6(-0.25,5.93) A7(0.25,5.93) A8(0.75,5.93) A9(1.25,5.93) A10(1.75,5.93) A11(2.25,5.93) A12(2.75,5.93)
  silkscreen extent -4.87,-0.03 4.87,7.28, body extent -4.87,-5.78 4.87,6.63, height 0.25
FP-AC0805KRX7R8BB104_0805-MFG [mm]
  rrect11% 0.95x1.4 smd paste+0 mask+0: 1(-0.925,0) 2(0.925,0)
  silkscreen extent -0.08,-0.72 0.08,0.72, body extent -1.6,-1.05 1.6,1.05, height 0.25
FP-ERA-3AEB104V_0603-MFG [mm]
  rrect15% 0.65x0.9 smd paste+0 mask+0: 1(-0.725,0) 2(0.725,0)
  silkscreen extent 0,-0.5 0,0.5, body extent -1.15,-0.6 1.15,0.6, height 0.25
FP-GCM1885C2A471JA16D_0603-MFG [mm]
  rrect15% 0.65x0.7 smd paste+0 mask+0: 1(-0.675,0) 2(0.675,0)
  silkscreen extent -0.8,-0.82 0.8,0.82, body extent -1.1,-0.55 1.1,0.55, height 0.25
FP-GMC21X5R226M35NT_0805-MFG [mil]
  rrect10% 40x50 smd paste+0 mask+0: 1(-40,0) 2(40,0)
  silkscreen extent -5,-29 5,29, body extent -64,-32 64,32, height 10
FP-GRMJN65C1H104GE01J_0704-MFG [mm] "Recommended Land Pattern"
  rrect14% 0.7x1 smd paste+0 mask+0: 1(-0.775,0) 2(0.775,0)
  silkscreen extent -0.05,-0.55 0.05,0.55, body extent -0.9,-0.5 0.9,0.5, height 0.65
FP-HTSW-103-07-F-S_HDR3-MFG [mm]
  rrect6% 1.57x1.57 hole 1.02 paste-2539.97 mask+0: 1(-2.54,0)
  round 1.57 hole 1.02 paste-2539.97 mask+0: 2(0,0) 3(2.54,0)
  silkscreen extent -3.88,-1.88 3.88,1.27, body extent -3.98,-1.37 3.98,1.37, height 0.25
FP-MLF1608DR68MTA00_0603-MFG [mm] "Recommended Land Pattern"
  rrect17% 0.6x0.8 smd paste+0 mask+0: 1(-0.7,0) 2(0.7,0)
  silkscreen extent -1,-0.77 1,0.77, body extent -0.8,-0.4 0.8,0.4, height 0.95
FP-PPTC031LGBN-RC_HDR3-MFG [mm]
  rrect6% 1.57x1.57 hole 1.02 paste-2539.97 mask+0: 1(-2.54,5.85)
  round 1.57 hole 1.02 paste-2539.97 mask+0: 2(0,5.85) 3(2.54,5.85)
  silkscreen extent -4.24,-4.4 4.24,7.3, body extent -4.34,-4.5 4.34,6.74, height 0.25
FP-RC0603FR-100RL_0603-MFG [mm]
  rrect13% 0.9x0.8 smd paste+0 mask+0: 1(-0.85,0) 2(0.85,0)
  silkscreen extent 0,-0.45 0,0.45, body extent -1.4,-0.55 1.4,0.55, height 0.25
Phoenix_1729160 [mm] "Phoenix Contact"
  rect 1.8x1.8 hole 1.3 paste-2539.97: 1(-12.7,0)
  round 1.8 hole 1.3 paste-2539.97: 2(-7.62,0) 3(-2.54,0) 4(2.54,0) 5(7.62,0) 6(12.7,0)
  silkscreen extent -15.81,-4.63 15.24,4.05, body extent -15.81,-4.05 15.24,4.05, height 10.01
RGT0016A-MFG [mm]
  rrect42% 0.6x0.24 smd paste+0 mask+0: 1(-1.4,0.75) 2(-1.4,0.25) 3(-1.4,-0.25) 4(-1.4,-0.75) 9(1.4,-0.75) 10(1.4,-0.25) 11(1.4,0.25) 12(1.4,0.75)
  rrect42% 0.24x0.6 smd paste+0 mask+0: 5(-0.75,-1.4) 6(-0.25,-1.4) 7(0.25,-1.4) 8(0.75,-1.4) 13(0.75,1.4) 14(0.25,1.4) 15(-0.25,1.4) 16(-0.75,1.4)
  rrect7% 1.45x1.45 smd paste-1000 mask+0: 17(0,0)
  silkscreen extent -2.4,-1.55 1.55,1.55, body extent -1.8,-1.8 1.8,1.8, height 0.25
SW_76SB06 [mm] "TH, 12-Leads, Body 9.65x17.3mm, Pitch 2.5mm"
  rect 1.35x1.35 hole 0.85: 1(-3.81,6.25)
  round 1.35 hole 0.85: 2(-3.81,3.75) 3(-3.81,1.25) 4(-3.81,-1.25) 5(-3.81,-3.75) 6(-3.81,-6.25) 7(3.81,-6.25) 8(3.81,-3.75) 9(3.81,-1.25) 10(3.81,1.25) 11(3.81,3.75) 12(3.81,6.25)
  silkscreen extent -5.25,-8.78 4.95,8.78, body extent -4.95,-8.78 4.95,8.78, height 7.98
TI_Stacked_Overlay_Small [mm]
  silkscreen extent -10.63,-2.49 10.63,2.49
WEEE_Minimum [mm] "WEEElie bin"
  silkscreen extent -2.42,-4.38 2.52,2.65

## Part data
C1 C2: library part CMP-0006975-4, "CAP, CERM, 0.01 uF, 25 V, +/- 5%, C0G/NP0, 0603", Cap_Case=0603, Manufacturer=Kemet, Supplier Part Number 1=399-5779-1-ND, TempCo=C0G/NP0, Tolerance_%=5%, Value1=Unknown, Value2=25V, ValueDisplayed=0.01uF
C3 C4 C5: library part CMP-0125654-1, "0.1 µF ±2% 50V Ceramic Capacitor C0G, NP0 0704 (1810 Metric)", Digikey Part Number=490-GRMJN65C1H104GE01JCT-ND, Manufacturer=Murata, Mouser Part Number=81-GRMJN65C1H104GE1J, Operating Temperature Range="-55°C to +125°C", TempCo=30ppm/°C, Temperature Characteristic=C0G, Tolerance_%=2%, ValueDisplayed=0.1uF
C6 C9: library part CMP-0120897-1, "22 µF ±20% 35V Ceramic Capacitor X5R 0805 (2012 Metric)", Digikey Part Number=4713-GMC21X5R226M35NTCT-ND, Manufacturer="Cal-Chip Electronics", Operating Temperature Range="-55°C to +85°C", TempCo=15%, Temperature Characteristic=X5R, Tolerance_%=20%, ValueDisplayed=22uF
C7 C8 C10 C11 C19 C22 C31 C32: library part CMP-0083854-1, "CAP, CERM, 0.1 µF, 50 V,+/- 5%, X7R, 0603", Cap_Case=0603, Manufacturer=AVX, TempCo=X7R, Tolerance_%=5%, Value2=50V, ValueDisplayed=0.1µF
C12 C20: library part CMP-0007159-4, "CAP, CERM, 1000 pF, 25 V, +/- 5%, C0G/NP0, 0603", Cap_Case=0603, Manufacturer=MuRata, Supplier Part Number 1=GRM1885C1E102JA01D-ND, TempCo=C0G/NP0, Tolerance_%=5%, Value1=Unknown, Value2=25V, ValueDisplayed=1000pF
C13 C28: library part CMP-0006910-4, "CAP, CERM, 270 pF, 50 V, +/- 5%, C0G/NP0, 0603", Cap_Case=0603, Manufacturer=Kemet, Supplier Part Number 1=399-1067-1-ND, TempCo=C0G/NP0, Tolerance_%=5%, Value1=Unknown, Value2=50V, ValueDisplayed=270pF
C14: library part CMP-0007497-5, "CAP, CERM, 10 uF, 10 V, +/- 20%, X7R, 0603", Cap_Case=0603, Manufacturer=MuRata, Supplier Part Number 1=81-GRM188Z71A106MA3D, TempCo=X7R, Tolerance_%=20%, Value1=Unknown, Value2=10V, ValueDisplayed=10uF
C15: library part CMP-0860544-1, "CAP, CERM, 0.01 µF, 6.3 V,+/- 10%, X7R, 0402", Cap_Case=0402, Manufacturer=Walsin, TempCo=X7R, Tolerance_%=10%, Value2=6.3V, ValueDisplayed=0.01µF
C16: library part CMP-0006622-2, "CAP, CERM, 0.01 uF, 6.3 V, +/- 10%, X7R, 0402", Cap_Case=0402, Manufacturer=MuRata, Supplier Part Number 1=GRM155R70J103KA01D-ND, TempCo=X7R, Tolerance_%=10%, Value1=Unknown, Value2=6.3V, ValueDisplayed=0.01uF
C17: library part CMP-0090211-1, "470pF ±5% 100V Ceramic Capacitor C0G, NP0 0603 (1608 Metric)", Digikey Part Number=490-4949-1-ND, Manufacturer="Murata Electronics North America", Mouser Part Number=81-GCM1885C2A471J16D, Operating Temperature Range="-55°C to +125°C", TempCo=30ppm/°C, Temperature Characteristic=C0G, Tolerance_%=5%, ValueDisplayed=470pF
C18: library part CMP-0007220-4, "CAP, CERM, 47 pF, 50 V, +/- 5%, C0G/NP0, 0603", Cap_Case=0603, Manufacturer=MuRata, Supplier Part Number 1=490-1419-1-ND, TempCo=C0G/NP0, Tolerance_%=5%, Value1=Unknown, Value2=50V, ValueDisplayed=47pF
C21: library part CMP-0007185-4, "CAP, CERM, 150 pF, 50 V, +/- 5%, C0G/NP0, 0603", Cap_Case=0603, Manufacturer=MuRata, Supplier Part Number 1=490-1431-1-ND, TempCo=C0G/NP0, Tolerance_%=5%, Value1=Unknown, Value2=50V, ValueDisplayed=150pF
C23 C24 C26 C29: library part CMP-0006763-4, "CAP, CERM, 100 pF, 50 V, +/- 5%, C0G/NP0, 0603", Cap_Case=0603, Manufacturer=AVX, Supplier Part Number 1=478-1175-1-ND, TempCo=C0G/NP0, Tolerance_%=5%, Value1="0.119 ohm", Value2=50V, ValueDisplayed=100pF
C25 C30: library part CMP-0007057-4, "CAP, CERM, 3.3 uF, 10 V, +/- 10%, X7S, 0603", Cap_Case=0603, Manufacturer=TDK, Supplier Part Number 1=445-14256-1-ND, TempCo=X7S, Tolerance_%=10%, Value1="0.004796 ohm", Value2=10V, ValueDisplayed=3.3uF
C27: library part CMP-0007209-4, "CAP, CERM, 330 pF, 50 V, +/- 5%, C0G/NP0, 0603", Cap_Case=0603, Manufacturer=MuRata, Supplier Part Number 1=490-1439-1-ND, TempCo=C0G/NP0, Tolerance_%=5%, Value1=Unknown, Value2=50V, ValueDisplayed=330pF
C36 C37: library part CMP-0121355-1, "0.1 µF ±10% 25V Ceramic Capacitor X7R 0805 (2012 Metric)", Digikey Part Number=311-3169-1-ND, Manufacturer=Yageo, Mouser Part Number=603-AC805KRX7R8BB104, Operating Temperature Range="-55°C to +125°C", TempCo=15%, Temperature Characteristic=X7R, Tolerance_%=10%, ValueDisplayed=100nF
J1 J2: library part CMP-0122423-2, "3 Position Header Connector 0.100\" (2.54mm) Through Hole, Right Angle Tin", Current_A=3A, Digikey Part Number=S5439-ND, Manufacturer=Sullins, Operating Temperature Range="-40°C to +105°C", Voltage_V=250V
J3: library part CMP-0055492-1, "Terminal Block, 6x1, 5.08mm, Th", Manufacturer="Phoenix Contact", Supplier Part Number 1=277-1251-ND
J4 J6 J7 J8 J9 J10: library part CMP-0096279-1, "Connector Header Through Hole 3 position 0.100\" (2.54mm)", Digikey Part Number=SAM10534-ND, Manufacturer=Samtec, Mouser Part Number=200-HTSW10307FS, Operating Temperature Range="-55°C to +125°C"
J5: library part CMP-0091586-1, "USB-C (USB TYPE-C) USB 3.2 Gen 2 (USB 3.1 Gen 2, Superspeed + (USB 3.1)) Receptacle Connector 24 Position Surface Mount, Right Angle; Through Hole", Current_A=5A, Digikey Part Number=732-9618-1-ND, Manufacturer=Wurth, Mouser Part Number=710-632723300011, Operating Temperature Range="-40°C to +105°C", Voltage_V=20V
L1: library part CMP-0125407-1, "Ind Power Shielded Multi-Layer 680nH 20% 25MHz 15Q-Factor Ferrite 70mA 0603 Punched Paper T/R", Digikey Part Number=445-6243-1-ND, Manufacturer=TDK, Mouser Part Number=810-MLF1608DR68MTA00, Operating Temperature Range="-55°C to +125°C", Self Resonant Frequency=150MHz, Test Frequency=25MHz, Tolerance_%=20%
Logo1: library part CMP-0074844-1
Logo2: library part CMP-0074838-1, "Texas Instrument Corporate Signature"
Logo4: library part CMP-0074769-1
R1: library part CMP-0046061-1, "Res Thin Film 0603 100K Ohm 0.1% 0.1W ±25ppm/°C Molded SMD Punched Carrier T/R", Digikey Part Number=P100KDBCT-ND, Manufacturer=Panasonic, Mouser Part Number=667-ERA-3AEB104V, Operating Temperature Range="-55°C to +155°C", Power=100mW, TempCo=25ppm/°C, Tolerance_%=0.1%
R2 R6: library part CMP-0023803-3, "RES, 16.0 k, 0.1%, 0.1 W, 0603", Manufacturer="Yageo America", Power_W=100mW, TempCo="25 ppm/C", Tolerance_%=0.1%, Value2=0.1W, Value_Code=16k0, ValueDisplayed=16.0k
R3 R5: library part CMP-0024266-3, "RES, 47.5 k, 0.1%, 0.1 W, 0603", Manufacturer="Yageo America", Power_W=100mW, TempCo="25 ppm/C", Tolerance_%=0.1%, Value2=0.1W, Value_Code=47k5, ValueDisplayed=47.5k
R4: library part CMP-0024525-2, "RES, 8.87 k, 0.1%, 0.1 W, 0603", Manufacturer="Yageo America", Power_W=100mW, TempCo="25 ppm/C", Tolerance_%=0.1%, Value2=0.1W, Value_Code=8k87, ValueDisplayed=8.87k
R7: library part CMP-0024307-2, "RES, 50.5 k, 0.1%, 0.1 W, 0603", Manufacturer="Yageo America", Power_W=100mW, TempCo="25 ppm/C", Tolerance_%=0.1%, Value2=0.1W, Value_Code=50k5, ValueDisplayed=50.5k
R8: library part CMP-0024558-2, "RES, 9.88 k, 0.1%, 0.1 W, 0603", Manufacturer="Yageo America", Power_W=100mW, TempCo="25 ppm/C", Tolerance_%=0.1%, Value2=0.1W, Value_Code=9k88, ValueDisplayed=9.88k
R9: library part CMP-0026717-1, "RES, 10.0, 1%, 0.063 W, 0402", Manufacturer=Rohm, Power_W=63mW, Supplier Part Number 1=RHM10.0LCT-ND, TempCo="100 ppm/C", Tolerance_%=1%, Value2=0.063W, Value_Code=10R0, ValueDisplayed=10.0
R10: library part CMP-0024436-2, "RES, 6.49 k, 0.1%, 0.1 W, 0603", Manufacturer="Yageo America", Power_W=100mW, TempCo="25 ppm/C", Tolerance_%=0.1%, Value2=0.1W, Value_Code=6k49, ValueDisplayed=6.49k
R11: library part CMP-0023567-3, "RES, 510, 0.1%, 0.1 W, 0603", Manufacturer="Susumu Co Ltd", Power_W=100mW, Supplier Part Number 1=RG16P510BCT-ND, TempCo="25 ppm/C", Tolerance_%=0.1%, Value2=0.1W, Value_Code=510R, ValueDisplayed=510
R12 R28: library part CMP-0024341-3, "RES, 562 k, 0.1%, 0.1 W, 0603", Manufacturer="Yageo America", Power_W=100mW, TempCo="25 ppm/C", Tolerance_%=0.1%, Value2=0.1W, Value_Code=562k
R13 R16 R23: library part CMP-0023468-3, "RES, 221, 0.1%, 0.1 W, 0603", Manufacturer="Susumu Co Ltd", Power_W=100mW, Supplier Part Number 1=RG16P221BCT-ND, TempCo="25 ppm/C", Tolerance_%=0.1%, Value2=0.1W, Value_Code=221R, ValueDisplayed=221
R14 R21: library part CMP-0023568-3, "RES, 5.10 k, 0.1%, 0.1 W, 0603", Manufacturer="Susumu Co Ltd", Power_W=100mW, Supplier Part Number 1=RG16P5.1KBCT-ND, TempCo="25 ppm/C", Tolerance_%=0.1%, Value2=0.1W, Value_Code=5k10, ValueDisplayed=5.10k
R15: library part CMP-0023097-5, "RES, 402, 1%, 0.1 W, 0603", Manufacturer=Yageo, Power_W=100mW, Supplier Part Number 1=311-402HRCT-ND, TempCo="100 ppm/C", Tolerance_%=1%, Value2=0.1W, Value_Code=402R, ValueDisplayed=402
R17: library part CMP-0023020-5, "RES, 30.0 k, 1%, 0.1 W, 0603", Manufacturer=Yageo, Power_W=100mW, Supplier Part Number 1=311-30.0KHRCT-ND, TempCo="100 ppm/C", Tolerance_%=1%, Value2=0.1W, Value_Code=30k0, ValueDisplayed=30.0k
R18: library part CMP-0023500-3, "RES, 270 k, 0.1%, 0.1 W, 0603", Manufacturer="Susumu Co Ltd", Power_W=100mW, Supplier Part Number 1=RG16P270KBCT-ND, TempCo="25 ppm/C", Tolerance_%=0.1%, Value2=0.1W, Value_Code=270k
R19: library part CMP-0023026-5, "RES, 31.6 k, 1%, 0.1 W, 0603", Manufacturer=Yageo, Power_W=100mW, Supplier Part Number 1=311-31.6KHRCT-ND, TempCo="100 ppm/C", Tolerance_%=1%, Value2=0.1W, Value_Code=31k6, ValueDisplayed=31.6k
R20 R24 R27: library part CMP-0123755-1, "0 Ohms Jumper Chip Resistor 0603 (1608 Metric) Moisture Resistant Thick Film", Digikey Part Number=13-RC0603FR-100RLCT-ND, Manufacturer=Yageo, Mouser Part Number=603-RC0603FR-100RL, Operating Temperature Range="-55°C to +155°C", Tolerance_%=1%
R22 R26: library part CMP-0080488-1, "RES, 10.0 k, 1%, 0.1 W, 0603", Manufacturer="TT Electronics/IRC", Power_W=100mW, TempCo="100 ppm/C", Tolerance_%=1%, Value2=0.1W, Value_Code=10k0, ValueDisplayed=10.0k
R25: library part CMP-0023577-3, "RES, 56.0 k, 0.1%, 0.1 W, 0603", Manufacturer="Susumu Co Ltd", Power_W=100mW, Supplier Part Number 1=RG16P56.0KBCT-ND, TempCo="25 ppm/C", Tolerance_%=0.1%, Value2=0.1W, Value_Code=56k0, ValueDisplayed=56.0k
R35: library part CMP-0024047-2, "RES, 294, 0.1%, 0.1 W, 0603", Manufacturer="Yageo America", Power_W=100mW, TempCo="25 ppm/C", Tolerance_%=0.1%, Value2=0.1W, Value_Code=294R, ValueDisplayed=294
R36 R37: library part CMP-0024148-3, "RES, 35.2, 0.1%, 0.1 W, 0603", Manufacturer="Yageo America", Power_W=100mW, TempCo="25 ppm/C", Tolerance_%=0.1%, Value2=0.1W, Value_Code=35R2, ValueDisplayed=35.2
R38: library part CMP-0024100-3, "RES, 30.5, 0.1%, 0.1 W, 0603", Manufacturer="Yageo America", Power_W=100mW, TempCo="25 ppm/C", Tolerance_%=0.1%, Value2=0.1W, Value_Code=30R5, ValueDisplayed=30.5
R39: library part CMP-0023661-3, "RES, 10.0, 0.1%, 0.1 W, 0603", Manufacturer="Yageo America", Power_W=100mW, TempCo="25 ppm/C", Tolerance_%=0.1%, Value2=0.1W, Value_Code=10R0, ValueDisplayed=10.0
R40: library part CMP-0023361-3, "RES, 100, 0.1%, 0.1 W, AEC-Q200 Grade 0, 0603", Manufacturer=Panasonic, Power_W=100mW, Supplier Part Number 1=P100DBCT-ND, TempCo="25 ppm/C", Tolerance_%=0.1%, Value2=0.1W, Value_Code=100R, ValueDisplayed=100
R41: library part CMP-0024262-3, "RES, 470 k, 0.1%, 0.1 W, 0603", Manufacturer="Yageo America", Power_W=100mW, TempCo="25 ppm/C", Tolerance_%=0.1%, Value2=0.1W, Value_Code=470k
R42 R43: library part CMP-0023559-3, "RES, 47.5 k, 0.1%, 0.1 W, 0603", Manufacturer="Susumu Co Ltd", Power_W=100mW, Supplier Part Number 1=RG16P47.5KBCT-ND, TempCo="25 ppm/C", Tolerance_%=0.1%, Value2=0.1W, Value_Code=47k5, ValueDisplayed=47.5k
SW1: library part CMP-0002309-1, "Switch, SPST, Off-On, 6 Pos, 0.15 A, 30 VDC, TH", CurrentRating_mA=150A, Manufacturer=Grayhill, Supplier Part Number 1=GH7173-ND
U1: library part CMP-0089145-1, "Instrumentation Amplifier 1 Circuit Rail-to-Rail 8-VSSOP", Digikey Part Number=296-23565-1-ND, Input Bias Current=0.00007uA, Input Offset Voltage=0.010-0.025mV, Manufacturer="Texas Instruments", Max Dual Supply Voltage=2.75V, Max Supply Voltage=5.5V, Min Dual Supply Voltage=900mV, Min Supply Voltage=1.8V, Mouser Part Number=595-INA333AIDGKT, Nominal Supply Current=50uA, Operating Temperature Range="-40°C to +125°C", Voltage Gain=0.001-1V/mV
U2: library part CMP-0072145-1, "Switched Capacitor Voltage Converter, 6-pin SOT-23, Pb-Free", Manufacturer="Texas Instruments", PackageTopMarking=S03A*XTT, PowerWise=N
U3: library part CMP-0122050-1, "80-MHz, Logarithmic Detector With Integrated Low-Noise Amplifier", Manufacturer="Texas Instruments", Max Supply Voltage=5.25V, Min Supply Voltage=3V, Operating Temperature Range="-40°C to +125°C"
U4 U7: library part CMP-0080747-1, "2-Channel, 1MHz, RRIO, 1.8V to 5.5V Operational Amplifier for Cost-Optimized Systems, D0008A (SOIC-8)", Alternate Manufacturer="Texas Instruments"
U5: library part CMP-0123245-1, "Single, 40-V, 5.25-MHz, 4-mV offset voltage, 20-V/µs, In to V+ op amp with -40°C to 125°C operation", Digikey Part Number=296-TL081HIDBVRTR-ND, Input Bias Current=1pA, Input Offset Voltage=1mV, Manufacturer="Texas Instruments", Max Supply Voltage=40V, Min Supply Voltage=4.5V, Mouser Part Number=595-TL081HIDBVR, Nominal Supply Current=960uA, Operating Temperature Range="-40°C to +125°C", Output Current Per Channel=26mA, Voltage Gain=125dB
